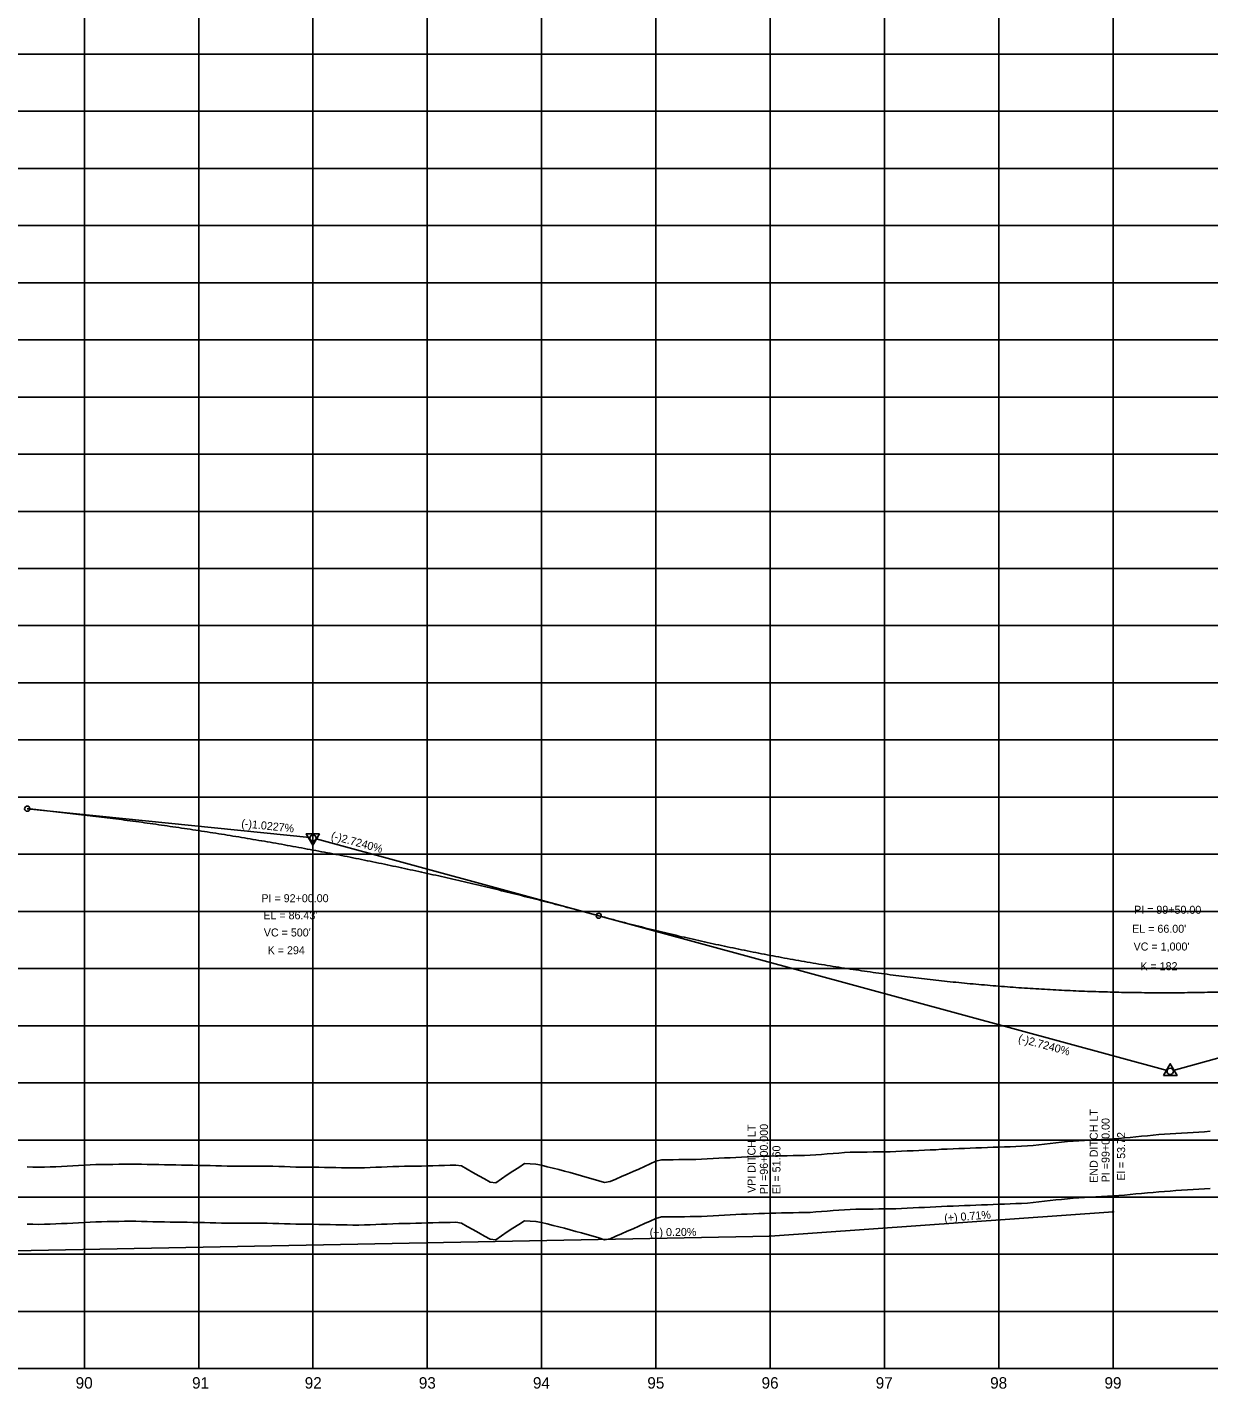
# Model space of a CAD drawing. Extents: x 2345490 to 2436403, y 465165 to 573888.
# Drawn here: x 2389272 to 2390305, y 564259 to 565450 of the extents above; entities that cross this region are included whole.
import ezdxf

# ---------------------------------------------------------------- set-up
doc = ezdxf.new("R2010")
doc.units = 0
for name, color, linetype in [('Old_Level_1', 7, 'Continuous'), ('Old_Level_2', 7, 'Continuous'), ('Old_Level_3', 7, 'Continuous'), ('Old_Level_57', 7, 'Continuous'), ('Old_Level_62', 7, 'Continuous'), ('Old_Level_63', 7, 'Continuous'), ('Prop PFL Text', 7, 'Continuous')]:
    doc.layers.add(name, color=color, linetype=linetype)

msp = doc.modelspace()

# ---------------------------------------------------------------- linework, layer by layer
at = {"layer": 'Old_Level_1'}
for points in [[(2389871.5425, 564410.2365), (2389876.5425, 564410.5485), (2389881.5425, 564410.827), (2389886.5425, 564411.0695), (2389891.5425, 564411.312), (2389896.5425, 564411.5545), (2389901.5425, 564411.797), (2389906.5425, 564412.0395), (2389911.5425, 564412.1925), (2389916.5425, 564412.33975), (2389921.5425, 564412.46975), (2389926.5425, 564412.581), (2389931.5425, 564412.692), (2389936.5425, 564412.80325), (2389941.5425, 564412.91175), (2389946.5425, 564412.998), (2389951.5425, 564413.0845), (2389956.5425, 564413.174), (2389961.5425, 564413.5715), (2389966.5425, 564413.96925), (2389971.5425, 564414.36675), (2389976.5425, 564414.76425), (2389981.5425, 564415.16175), (2389986.5425, 564415.55925), (2389991.5425, 564415.75075), (2389996.5425, 564415.88525), (2390001.5425, 564415.95875), (2390006.5425, 564416.032), (2390011.5425, 564416.1055), (2390016.5425, 564416.179), (2390021.5425, 564416.2525), (2390026.5425, 564416.326), (2390031.5425, 564416.4555), (2390036.5425, 564416.68725), (2390041.5425, 564416.919), (2390046.5425, 564417.15075), (2390051.5425, 564417.3825), (2390056.5425, 564417.6145), (2390061.5425, 564417.84625), (2390066.5425, 564418.07875), (2390071.5425, 564418.38475), (2390076.5425, 564418.57825), (2390081.5425, 564418.7715), (2390086.5425, 564418.965), (2390091.5425, 564419.15825), (2390096.5425, 564419.35175), (2390101.5425, 564419.54525), (2390106.5425, 564419.7385), (2390111.5425, 564419.932), (2390116.5425, 564420.12525), (2390121.5425, 564420.31875), (2390126.5425, 564420.51225), (2390131.5425, 564420.7055), (2390136.5425, 564420.899), (2390141.5425, 564421.09225), (2390146.5425, 564421.29325), (2390151.5425, 564421.84775), (2390156.5425, 564422.4005), (2390161.5425, 564422.9535), (2390166.5425, 564423.5065), (2390171.5425, 564424.0595), (2390176.5425, 564424.6125), (2390181.5425, 564425.16525), (2390186.5425, 564425.65475), (2390191.5425, 564425.932), (2390196.5425, 564426.20925), (2390201.5425, 564426.48625), (2390206.5425, 564426.7635), (2390211.5425, 564427.04075), (2390216.5425, 564427.318), (2390221.5425, 564427.595), (2390226.5425, 564427.90175), (2390231.5425, 564428.37525), (2390236.5425, 564428.849), (2390241.5425, 564429.3225), (2390246.5425, 564429.796), (2390251.5425, 564430.2695), (2390256.5425, 564430.74325), (2390261.5425, 564431.21675), (2390266.5425, 564431.585), (2390271.5425, 564431.89975), (2390276.5425, 564432.2145), (2390281.5425, 564432.5295), (2390286.5425, 564432.84425), (2390291.5425, 564433.159), (2390296.5425, 564433.474), (2390301.5425, 564433.812), (2390306.5425, 564434.1725)], [(2389271.5425, 564402.95025), (2389276.5425, 564402.8135), (2389281.5425, 564402.6765), (2389286.5425, 564402.8155), (2389291.5425, 564402.983), (2389296.5425, 564403.15), (2389301.5425, 564403.346), (2389306.5425, 564403.6275), (2389311.5425, 564403.909), (2389316.5425, 564404.19), (2389321.5425, 564404.471), (2389326.5425, 564404.752), (2389331.5425, 564404.959), (2389336.5425, 564405.0555), (2389341.5425, 564405.15175), (2389346.5425, 564405.248), (2389351.5425, 564405.344), (2389356.5425, 564405.436), (2389361.5425, 564405.41075), (2389366.5425, 564405.3855), (2389371.5425, 564405.29925)], [(2389371.5425, 564405.29925), (2389376.5425, 564405.17375), (2389381.5425, 564405.04925), (2389386.5425, 564404.96025), (2389391.5425, 564404.8715), (2389396.5425, 564404.7825), (2389401.5425, 564404.69375), (2389406.5425, 564404.605), (2389411.5425, 564404.51625), (2389416.5425, 564404.42775), (2389421.5425, 564404.339), (2389426.5425, 564404.2505), (2389431.5425, 564404.162), (2389436.5425, 564404.0415), (2389441.5425, 564403.915), (2389446.5425, 564403.79225), (2389451.5425, 564403.74125), (2389456.5425, 564403.69025), (2389461.5425, 564403.6485), (2389466.5425, 564403.64725), (2389471.5425, 564403.64625), (2389476.5425, 564403.64525), (2389481.5425, 564403.6445), (2389486.5425, 564403.59975), (2389491.5425, 564403.455), (2389496.5425, 564403.27025), (2389501.5425, 564403.08575), (2389506.5425, 564402.9015), (2389511.5425, 564402.7825), (2389516.5425, 564402.77), (2389521.5425, 564402.7575), (2389526.5425, 564402.6955), (2389531.5425, 564402.58275), (2389536.5425, 564402.47), (2389541.5425, 564402.37975), (2389546.5425, 564402.3025), (2389551.5425, 564402.22525), (2389556.5425, 564402.148), (2389561.5425, 564402.094), (2389566.5425, 564402.25325), (2389571.5425, 564402.4305), (2389576.5425, 564402.629), (2389581.5425, 564402.82775), (2389586.5425, 564403.02625), (2389591.5425, 564403.22075), (2389596.5425, 564403.39975), (2389601.5425, 564403.576), (2389606.5425, 564403.61625), (2389611.5425, 564403.65675), (2389616.5425, 564403.78825), (2389621.5425, 564403.9325), (2389626.5425, 564404.07675), (2389631.5425, 564404.221), (2389636.5425, 564404.347), (2389641.5425, 564404.4595), (2389646.5425, 564404.5725), (2389651.5425, 564403.859), (2389656.5425, 564400.98925), (2389661.5425, 564398.115), (2389666.5425, 564395.23625), (2389671.5425, 564392.44075), (2389676.5425, 564389.6835), (2389681.5425, 564389.066), (2389686.5425, 564392.70575), (2389691.5425, 564396.13225), (2389696.5425, 564399.30525), (2389701.5425, 564402.54975), (2389706.5425, 564405.83575), (2389711.5425, 564405.6055), (2389716.5425, 564405.3775), (2389721.5425, 564404.502), (2389726.5425, 564403.1505), (2389731.5425, 564401.86275), (2389736.5425, 564400.59425), (2389741.5425, 564399.32675), (2389746.5425, 564397.96125), (2389751.5425, 564396.58425), (2389756.5425, 564395.20725), (2389761.5425, 564393.8305), (2389766.5425, 564392.294), (2389771.5425, 564390.865), (2389776.5425, 564389.26775), (2389781.5425, 564390.167), (2389786.5425, 564392.3445), (2389791.5425, 564394.52175), (2389796.5425, 564396.69925), (2389801.5425, 564398.87675), (2389806.5425, 564401.13175), (2389811.5425, 564403.4), (2389816.5425, 564405.6685), (2389821.5425, 564407.93675), (2389826.5425, 564409.18375), (2389831.5425, 564409.2605), (2389836.5425, 564409.32175), (2389841.5425, 564409.383), (2389846.5425, 564409.4445), (2389851.5425, 564409.50575), (2389856.5425, 564409.567), (2389861.5425, 564409.62825), (2389866.5425, 564409.9245), (2389871.5425, 564410.2365)]]:
    msp.add_lwpolyline(points, dxfattribs=at)
at = {"layer": 'Old_Level_2'}
for p, q in [((2389271.5425, 564766.4005), (2389518.807, 564741.11375)), ((2389771.5425, 564672.734), (2389524.196, 564740.111)), ((2389771.5425, 564672.734), (2390268.88925, 564537.25675)), ((2390771.5425, 564675.6185), (2390274.192, 564537.27075))]:
    msp.add_line(p, q, dxfattribs=at)
for points in [[(2389527.36775, 564744.4875), (2389515.62525, 564744.473), (2389521.50875, 564734.35475)], [(2390265.75075, 564533.1055), (2390277.49325, 564533.1055), (2390271.62225, 564543.23125)]]:
    msp.add_lwpolyline(points, close=True, dxfattribs=at)
for centre, radius in [((2389271.5425, 564766.4005), 2.25), ((2389521.5425, 564740.834), 2.75), ((2389771.5425, 564672.734), 2.25), ((2390271.5425, 564536.534), 2.75)]:
    msp.add_circle(centre, radius, dxfattribs=at)
for points in [[(2389271.5425, 564766.4005), (2389281.5425, 564765.36075), (2389291.5425, 564764.28725), (2389301.5425, 564763.1795), (2389311.5425, 564762.03775), (2389321.5425, 564760.862), (2389331.5425, 564759.652), (2389341.5425, 564758.40825), (2389351.5425, 564757.13025), (2389361.5425, 564755.8185), (2389371.5425, 564754.4725), (2389381.5425, 564753.0925), (2389391.5425, 564751.6785), (2389401.5425, 564750.2305), (2389411.5425, 564748.7485), (2389421.5425, 564747.2325), (2389431.5425, 564745.6825), (2389441.5425, 564744.09825), (2389451.5425, 564742.48025), (2389461.5425, 564740.828), (2389471.5425, 564739.142), (2389481.5425, 564737.42175), (2389491.5425, 564735.6675), (2389501.5425, 564733.87925), (2389511.5425, 564732.05675), (2389521.5425, 564730.2005), (2389531.5425, 564728.31025), (2389541.5425, 564726.38575), (2389551.5425, 564724.4275), (2389561.5425, 564722.435), (2389571.5425, 564720.4085), (2389581.5425, 564718.348), (2389591.5425, 564716.2535), (2389601.5425, 564714.125), (2389611.5425, 564711.9625), (2389621.5425, 564709.766), (2389631.5425, 564707.53525), (2389641.5425, 564705.2705), (2389651.5425, 564702.972), (2389661.5425, 564700.63925), (2389671.5425, 564698.2725), (2389681.5425, 564695.87175), (2389691.5425, 564693.437), (2389701.5425, 564690.96825), (2389711.5425, 564688.4655), (2389721.5425, 564685.9285), (2389731.5425, 564683.35775), (2389741.5425, 564680.75275), (2389751.5425, 564678.11375), (2389761.5425, 564675.44075), (2389771.5425, 564672.734)], [(2389771.5425, 564672.734), (2389791.5425, 564667.396), (2389811.5425, 564662.27825), (2389831.5425, 564657.381), (2389851.5425, 564652.70375), (2389871.5425, 564648.24675), (2389891.5425, 564644.01), (2389911.5425, 564639.9935), (2389931.5425, 564636.19725), (2389951.5425, 564632.621), (2389971.5425, 564629.26525), (2389991.5425, 564626.12975), (2390011.5425, 564623.21425), (2390031.5425, 564620.519), (2390051.5425, 564618.04425), (2390071.5425, 564615.7895), (2390091.5425, 564613.755), (2390111.5425, 564611.94075), (2390131.5425, 564610.34675), (2390151.5425, 564608.973), (2390171.5425, 564607.8195), (2390191.5425, 564606.886), (2390211.5425, 564606.173), (2390231.5425, 564605.68), (2390251.5425, 564605.4075), (2390271.5425, 564605.355), (2390291.5425, 564605.52275), (2390311.5425, 564605.91075), (2390331.5425, 564606.519), (2390351.5425, 564607.3475), (2390371.5425, 564608.39625), (2390391.5425, 564609.66525), (2390411.5425, 564611.1545), (2390431.5425, 564612.86375), (2390451.5425, 564614.7935), (2390471.5425, 564616.94325), (2390491.5425, 564619.31325), (2390511.5425, 564621.90375), (2390531.5425, 564624.71425), (2390551.5425, 564627.745), (2390571.5425, 564630.996), (2390591.5425, 564634.46725), (2390611.5425, 564638.1585), (2390631.5425, 564642.07025), (2390651.5425, 564646.20225), (2390671.5425, 564650.55425), (2390691.5425, 564655.12675), (2390711.5425, 564659.91925), (2390731.5425, 564664.932), (2390751.5425, 564670.165), (2390771.5425, 564675.6185)]]:
    msp.add_spline(points, degree=3, dxfattribs=at)
at = {"layer": 'Old_Level_3'}
for p, q in [((2389921.5425, 564392.534), (2390221.5425, 564413.734)), ((2389101.5425, 564376.534), (2389921.5425, 564392.534))]:
    msp.add_line(p, q, dxfattribs=at)
for centre in [(2390221.5425, 564413.734), (2389921.5425, 564392.534)]:
    msp.add_circle(centre, 0.5, dxfattribs=at)
at = {"layer": 'Old_Level_57'}
for p, q in [((2389321.5425, 564276.534), (2389321.5425, 566615.2835)), ((2389421.5425, 564276.534), (2389421.5425, 566615.2835)), ((2389521.54225, 564276.534), (2389521.54225, 566615.2835)), ((2389621.54225, 564276.534), (2389621.54225, 566615.2835)), ((2389721.54225, 564276.534), (2389721.54225, 566615.2835)), ((2389821.54225, 564276.534), (2389821.54225, 566615.2835)), ((2389921.5425, 564276.534), (2389921.5425, 566615.2835)), ((2390021.54225, 564276.534), (2390021.54225, 566615.2835)), ((2390121.54225, 564276.534), (2390121.54225, 566615.2835)), ((2390221.54225, 564276.534), (2390221.54225, 566615.2835)), ((2381271.5425, 565426.534), (2410861.12275, 565426.534)), ((2381271.5425, 565376.534), (2410861.12275, 565376.534)), ((2381271.5425, 565326.534), (2410861.12275, 565326.534)), ((2381271.5425, 565276.534), (2410861.12275, 565276.534)), ((2381271.5425, 565226.534), (2410861.12275, 565226.534)), ((2381271.5425, 565176.534), (2410861.12275, 565176.534)), ((2381271.5425, 565126.534), (2410861.12275, 565126.534)), ((2381271.5425, 565076.534), (2410861.12275, 565076.534)), ((2381271.5425, 565026.534), (2410861.12275, 565026.534)), ((2381271.5425, 564976.534), (2410861.12275, 564976.534)), ((2381271.5425, 564926.534), (2410861.12275, 564926.534)), ((2381271.5425, 564876.534), (2410861.12275, 564876.534)), ((2381271.5425, 564826.534), (2410861.12275, 564826.534)), ((2381271.54275, 564776.534), (2410861.123, 564776.534)), ((2381271.5425, 564726.534), (2410861.12275, 564726.534)), ((2381271.54275, 564676.534), (2410861.123, 564676.534)), ((2381271.5425, 564626.534), (2410861.12275, 564626.534)), ((2381271.54275, 564576.534), (2410861.123, 564576.534)), ((2381271.5425, 564526.534), (2410861.12275, 564526.534)), ((2381271.54275, 564476.534), (2410861.123, 564476.534)), ((2381271.5425, 564426.534), (2410861.12275, 564426.534)), ((2381271.54275, 564376.534), (2410861.123, 564376.534)), ((2381271.5425, 564326.534), (2410861.12275, 564326.534)), ((2381271.54275, 564276.534), (2410861.123, 564276.534))]:
    msp.add_line(p, q, dxfattribs=at)
at = {"layer": 'Old_Level_63'}
msp.add_line((2381321.5425, 564276.534), (2406689.937, 564276.534), dxfattribs=at)
for points in [[(2389871.5425, 564460.23625), (2389876.5425, 564460.54825), (2389881.5425, 564460.82675), (2389886.5425, 564461.06925), (2389891.5425, 564461.31175), (2389896.5425, 564461.55425), (2389901.5425, 564461.79675), (2389906.5425, 564462.03925), (2389911.5425, 564462.19225), (2389916.5425, 564462.3395), (2389921.5425, 564462.4695), (2389926.5425, 564462.58075), (2389931.5425, 564462.69175), (2389936.5425, 564462.803), (2389941.5425, 564462.9115), (2389946.5425, 564462.99775), (2389951.5425, 564463.08425), (2389956.5425, 564463.17375), (2389961.5425, 564463.57125), (2389966.5425, 564463.969), (2389971.5425, 564464.3665), (2389976.5425, 564464.764), (2389981.5425, 564465.1615), (2389986.5425, 564465.559), (2389991.5425, 564465.7505), (2389996.5425, 564465.885), (2390001.5425, 564465.9585), (2390006.5425, 564466.03175), (2390011.5425, 564466.10525), (2390016.5425, 564466.17875), (2390021.5425, 564466.25225), (2390026.5425, 564466.32575), (2390031.5425, 564466.45525), (2390036.5425, 564466.687), (2390041.5425, 564466.91875), (2390046.5425, 564467.1505), (2390051.5425, 564467.38225), (2390056.5425, 564467.61425), (2390061.5425, 564467.846), (2390066.5425, 564468.0785), (2390071.5425, 564468.3845), (2390076.5425, 564468.578), (2390081.5425, 564468.77125), (2390086.5425, 564468.96475), (2390091.5425, 564469.158), (2390096.5425, 564469.3515), (2390101.5425, 564469.545), (2390106.5425, 564469.73825), (2390111.5425, 564469.93175), (2390116.5425, 564470.125), (2390121.5425, 564470.3185), (2390126.5425, 564470.512), (2390131.5425, 564470.70525), (2390136.5425, 564470.89875), (2390141.5425, 564471.092), (2390146.5425, 564471.293), (2390151.5425, 564471.8475), (2390156.5425, 564472.40025), (2390161.5425, 564472.95325), (2390166.5425, 564473.50625), (2390171.5425, 564474.05925), (2390176.5425, 564474.61225), (2390181.5425, 564475.165), (2390186.5425, 564475.6545), (2390191.5425, 564475.93175), (2390196.5425, 564476.209), (2390201.5425, 564476.486), (2390206.5425, 564476.76325), (2390211.5425, 564477.0405), (2390216.5425, 564477.31775), (2390221.5425, 564477.59475), (2390226.5425, 564477.9015), (2390231.5425, 564478.375), (2390236.5425, 564478.84875), (2390241.5425, 564479.32225), (2390246.5425, 564479.79575), (2390251.5425, 564480.26925), (2390256.5425, 564480.743), (2390261.5425, 564481.2165), (2390266.5425, 564481.58475), (2390271.5425, 564481.8995), (2390276.5425, 564482.21425), (2390281.5425, 564482.52925), (2390286.5425, 564482.844), (2390291.5425, 564483.15875), (2390296.5425, 564483.47375), (2390301.5425, 564483.81175), (2390306.5425, 564484.17225)], [(2389271.5425, 564452.95), (2389276.5425, 564452.81325), (2389281.5425, 564452.67625), (2389286.5425, 564452.81525), (2389291.5425, 564452.98275), (2389296.5425, 564453.14975), (2389301.5425, 564453.34575), (2389306.5425, 564453.62725), (2389311.5425, 564453.90875), (2389316.5425, 564454.18975), (2389321.5425, 564454.47075), (2389326.5425, 564454.75175), (2389331.5425, 564454.95875), (2389336.5425, 564455.05525), (2389341.5425, 564455.1515), (2389346.5425, 564455.24775), (2389351.5425, 564455.34375), (2389356.5425, 564455.43575), (2389361.5425, 564455.4105), (2389366.5425, 564455.38525), (2389371.5425, 564455.299)], [(2389371.5425, 564455.299), (2389376.5425, 564455.1735), (2389381.5425, 564455.049), (2389386.5425, 564454.96), (2389391.5425, 564454.87125), (2389396.5425, 564454.78225), (2389401.5425, 564454.6935), (2389406.5425, 564454.60475), (2389411.5425, 564454.516), (2389416.5425, 564454.4275), (2389421.5425, 564454.33875), (2389426.5425, 564454.25025), (2389431.5425, 564454.16175), (2389436.5425, 564454.04125), (2389441.5425, 564453.91475), (2389446.5425, 564453.792), (2389451.5425, 564453.741), (2389456.5425, 564453.69), (2389461.5425, 564453.64825), (2389466.5425, 564453.647), (2389471.5425, 564453.646), (2389476.5425, 564453.645), (2389481.5425, 564453.64425), (2389486.5425, 564453.5995), (2389491.5425, 564453.45475), (2389496.5425, 564453.27), (2389501.5425, 564453.0855), (2389506.5425, 564452.90125), (2389511.5425, 564452.78225), (2389516.5425, 564452.76975), (2389521.5425, 564452.75725), (2389526.5425, 564452.69525), (2389531.5425, 564452.5825), (2389536.5425, 564452.46975), (2389541.5425, 564452.3795), (2389546.5425, 564452.30225), (2389551.5425, 564452.225), (2389556.5425, 564452.14775), (2389561.5425, 564452.09375), (2389566.5425, 564452.253), (2389571.5425, 564452.43025), (2389576.5425, 564452.62875), (2389581.5425, 564452.8275), (2389586.5425, 564453.026), (2389591.5425, 564453.2205), (2389596.5425, 564453.3995), (2389601.5425, 564453.57575), (2389606.5425, 564453.616), (2389611.5425, 564453.6565), (2389616.5425, 564453.788), (2389621.5425, 564453.93225), (2389626.5425, 564454.0765), (2389631.5425, 564454.22075), (2389636.5425, 564454.34675), (2389641.5425, 564454.45925), (2389646.5425, 564454.57225), (2389651.5425, 564453.85875), (2389656.5425, 564450.989), (2389661.5425, 564448.11475), (2389666.5425, 564445.236), (2389671.5425, 564442.4405), (2389676.5425, 564439.68325), (2389681.5425, 564439.06575), (2389686.5425, 564442.7055), (2389691.5425, 564446.132), (2389696.5425, 564449.305), (2389701.5425, 564452.5495), (2389706.5425, 564455.8355), (2389711.5425, 564455.60525), (2389716.5425, 564455.37725), (2389721.5425, 564454.50175), (2389726.5425, 564453.15025), (2389731.5425, 564451.8625), (2389736.5425, 564450.594), (2389741.5425, 564449.3265), (2389746.5425, 564447.961), (2389751.5425, 564446.584), (2389756.5425, 564445.207), (2389761.5425, 564443.83025), (2389766.5425, 564442.29375), (2389771.5425, 564440.86475), (2389776.5425, 564439.2675), (2389781.5425, 564440.16675), (2389786.5425, 564442.34425), (2389791.5425, 564444.5215), (2389796.5425, 564446.699), (2389801.5425, 564448.8765), (2389806.5425, 564451.1315), (2389811.5425, 564453.39975), (2389816.5425, 564455.66825), (2389821.5425, 564457.9365), (2389826.5425, 564459.1835), (2389831.5425, 564459.26025), (2389836.5425, 564459.3215), (2389841.5425, 564459.38275), (2389846.5425, 564459.44425), (2389851.5425, 564459.5055), (2389856.5425, 564459.56675), (2389861.5425, 564459.628), (2389866.5425, 564459.92425), (2389871.5425, 564460.23625)]]:
    msp.add_lwpolyline(points, dxfattribs=at)
at = {"layer": 'Prop PFL Text'}
for p, q in [((2390221.5425, 564413.734), (2390221.5425, 564521.0307)), ((2389921.5425, 564392.534), (2389921.5425, 564497.73258))]:
    msp.add_line(p, q, dxfattribs=at)

# ---------------------------------------------------------------- texts
at = {"layer": 'Old_Level_2'}
for s, rotation, p in [('(-)1.0227%', 354.16085, (2389458.5905, 564750.28725)), ('(-)2.7240%', 344.76233611, (2389536.7845, 564739.79125)), ('(-)2.7240%', 344.76233611, (2390138.06369, 564562.50171))]:
    msp.add_text(s, height=7.000001, rotation=rotation, dxfattribs=at).set_placement(p)
for s, height, p in [('PI = 92+00.00', 7.0000005, (2389476.39475, 564684.56125)), ('PI = 99+50.00', 7.0000005, (2390239.91525, 564674.473)), ("EL = 86.43'", 7.0000005, (2389478.08075, 564669.622)), ("VC = 500'", 7.000001, (2389478.5105, 564654.59275)), ("EL = 66.00'", 7.0000005, (2390238.22875, 564657.847)), ('K = 294', 7.000001, (2389481.883, 564639.0715)), ("VC = 1,000'", 7.0000005, (2390239.50175, 564642.3165)), ('K = 182', 7.000001, (2390245.404, 564625.108))]:
    msp.add_text(s, height=height, dxfattribs=at).set_placement(p)
at = {"layer": 'Old_Level_3'}
for s, height, rotation, p in [('END DITCH LT', 7.0000005, 90, (2390208.13251, 564439.06625)), ('VPI DITCH LT', 7.0000005, 90, (2389908.71482, 564430.23194)), ('PI =96+00.000', 7.0000005, 90, (2389919.5425, 564429.2476)), ('PI =99+00.00', 7.0000005, 90, (2390218.50001, 564439.52378)), ('El = 53.72', 7.000001, 90, (2390232.10623, 564441.08751)), ('El = 51.60', 7.000001, 90, (2389930.5425, 564429.2476)), ('(+) 0.71%', 7, 4.39870556, (2390074.11477, 564404.77137)), ('(+) 0.20%', 7.000001, 0.44676187, (2389816.14393, 564392.36072))]:
    msp.add_text(s, height=height, rotation=rotation, dxfattribs=at).set_placement(p)
at = {"layer": 'Old_Level_62'}
for s, p in [('90', (2389313.929, 564259.034)), ('91', (2389415.7685, 564259.034)), ('92', (2389514.31675, 564259.034)), ('93', (2389614.1515, 564259.034)), ('94', (2389713.994, 564259.034)), ('95', (2389814.0865, 564259.034)), ('96', (2389914.0275, 564259.034)), ('97', (2390013.885, 564259.034)), ('98', (2390114.01075, 564259.034)), ('99', (2390214.053, 564259.034))]:
    msp.add_text(s, height=10.000001, dxfattribs=at).set_placement(p)

doc.saveas('drawing.dxf')
